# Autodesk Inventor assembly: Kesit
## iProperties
Shininess: 64.0
Length Units: 11269
Angle Units: 11279
Time Units: 11290
Mass Units: 11283
Length Display Precision: 3
Angle Display Precision: 2
Compacted: True
Created: 2004-01
Part Number: Kesit
Document SubType Name: Assembly
Designer: Administrator
Manufacturer: Standard
Standards Organization: Custom
Density: 0.0
Volumn: 0.0
Area: 0.0
PropertySet Name: Model Information
Control State: 0
Master: False
Checked Out: False
Author: Administrator
